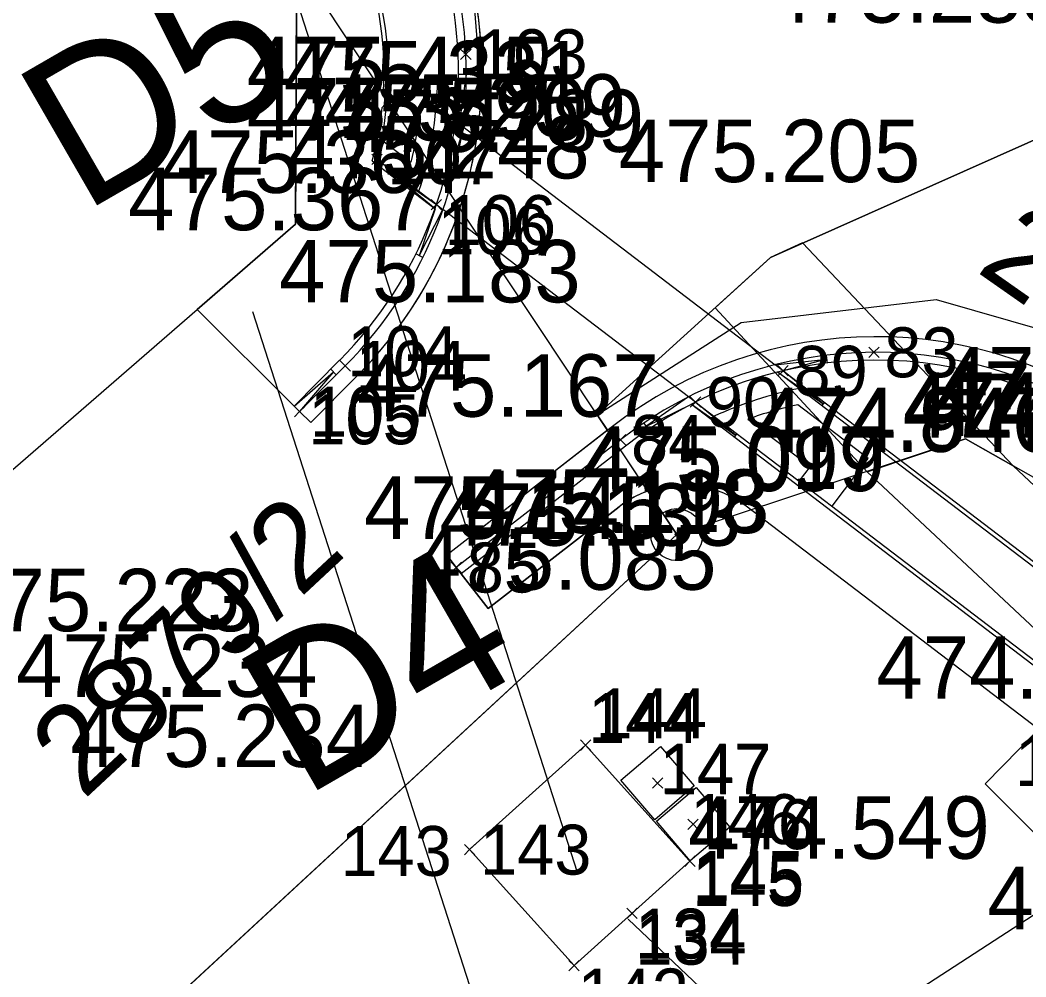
# Model space of a CAD drawing. Extents: x -758836 to -757729, y -1175316 to -1174366.
# Drawn here: x -758436.44 to -758417.1, y -1174844.78 to -1174826.39 of the extents above; entities that cross this region are included whole.
import ezdxf

# ---------------------------------------------------------------- set-up
doc = ezdxf.new("R2010")
doc.units = 0
for name, color, linetype in [('__NOR-dočasný zábor', 7, 'Continuous'), ('_NOR-návrh silná', 7, 'Continuous'), ('_NOR-návrh tenká', 7, 'Continuous'), ('_NOR-popis', 7, 'Continuous'), ('_vytyčený bod', 7, 'Continuous'), ('G_Obvod stavby', 7, 'Continuous'), ('Hranice parcel', 7, 'Continuous'), ('KOS_kabely SSZT', 7, 'Continuous'), ('KOS_PZZ nové', 7, 'Continuous'), ('Parcelní čísla', 7, 'Continuous'), ('Vnitřní kresba', 7, 'Continuous'), ('Vrstva 61', 7, 'Continuous'), ('Věcná břemena k části', 7, 'Continuous'), ('Značky bodu BP', 7, 'Continuous')]:
    doc.layers.add(name, color=color, linetype=linetype)

msp = doc.modelspace()

# ---------------------------------------------------------------- linework, layer by layer
at = {"layer": '__NOR-dočasný zábor'}
for p, q in [((-758431.14, -1174830.31), (-758431.12, -1174825.29)), ((-758433.036, -1174831.952), (-758431.14, -1174830.31)), ((-758431.169, -1174833.809), (-758433.036, -1174831.952)), ((-758429.975, -1174833.247), (-758430.85, -1174834.126)), ((-758431.063, -1174833.915), (-758431.169, -1174833.809)), ((-758430.85, -1174834.126), (-758431.063, -1174833.915)), ((-758425.144, -1174834.274), (-758428.234, -1174836.675)), ((-758424.978, -1174834.525), (-758425.144, -1174834.274)), ((-758424.894, -1174834.65), (-758424.978, -1174834.525)), ((-758424.368, -1174835.441), (-758424.894, -1174834.65)), ((-758428.234, -1174836.675), (-758428.05, -1174836.912)), ((-758428.05, -1174836.912), (-758427.958, -1174837.03))]:
    msp.add_line(p, q, dxfattribs=at)
msp.add_lwpolyline([(-758427.958, -1174837.03), (-758427.436, -1174837.702), (-758424.916, -1174835.743)], dxfattribs=at)
for centre, radius, start, end in [((-758435.859, -1174827.393), 8.3, 341.6371, 49.8317), ((-758435.859, -1174827.393), 8.3, 315.1499, 341.6371), ((-758423.689, -1174837.322), 2, 109.854, 127.8448)]:
    msp.add_arc(centre, radius, start, end, dxfattribs=at)
at = {"layer": '_NOR-návrh silná'}
for p, q in [((-758430.188, -1174833.035), (-758431.063, -1174833.915)), ((-758421.766, -1174833.13), (-758401.3, -1174848.727)), ((-758423.45, -1174833.732), (-758401.745, -1174850.274))]:
    msp.add_line(p, q, dxfattribs=at)
for points in [[(-758429.577, -1174829.063), (-758428.432, -1174829.935)], [(-758424.891, -1174834.458), (-758428.05, -1174836.912)]]:
    msp.add_lwpolyline(points, dxfattribs=at)
for centre, radius, start, end in [((-758435.859, -1174827.393), 8, 315.1499, 49.8317), ((-758435.859, -1174827.393), 6.5, 345.1172, 49.8317), ((-758419.983, -1174840.775), 8, 52.6885, 127.8448)]:
    msp.add_arc(centre, radius, start, end, dxfattribs=at)
at = {"layer": '_NOR-návrh tenká'}
for p, q in [((-758427.86, -1174827.437), (-758428.01, -1174827.437)), ((-758427.996, -1174828.382), (-758428.01, -1174827.437)), ((-758427.86, -1174827.437), (-758427.996, -1174828.382)), ((-758428.065, -1174828.329), (-758427.927, -1174828.434)), ((-758427.927, -1174828.434), (-758421.919, -1174833.013)), ((-758429.228, -1174829.329), (-758429.276, -1174829.393)), ((-758428.46, -1174830.015), (-758429.252, -1174829.361)), ((-758429.252, -1174829.361), (-758428.432, -1174829.935)), ((-758428.432, -1174829.935), (-758428.307, -1174830.031)), ((-758428.46, -1174830.015), (-758428.762, -1174830.918)), ((-758428.762, -1174830.918), (-758428.307, -1174830.031)), ((-758423.583, -1174833.631), (-758428.307, -1174830.031)), ((-758428.694, -1174830.952), (-758428.829, -1174830.885)), ((-758420.937, -1174832.832), (-758420.919, -1174832.981)), ((-758430.294, -1174832.929), (-758431.169, -1174833.809)), ((-758421.919, -1174833.013), (-758420.928, -1174832.907)), ((-758421.766, -1174833.13), (-758421.919, -1174833.013)), ((-758420.928, -1174832.907), (-758421.766, -1174833.13)), ((-758431.169, -1174833.809), (-758430.411, -1174833.153)), ((-758430.411, -1174833.153), (-758431.063, -1174833.915)), ((-758430.464, -1174833.1), (-758430.358, -1174833.206)), ((-758421.866, -1174833.154), (-758420.994, -1174833.768)), ((-758420.994, -1174833.768), (-758421.766, -1174833.13)), ((-758423.583, -1174833.631), (-758424.404, -1174834.198)), ((-758424.404, -1174834.198), (-758423.53, -1174833.772)), ((-758423.45, -1174833.732), (-758423.583, -1174833.631)), ((-758423.53, -1174833.772), (-758422.679, -1174834.37)), ((-758422.679, -1174834.37), (-758423.45, -1174833.732)), ((-758420.97, -1174833.736), (-758421.019, -1174833.8)), ((-758431.169, -1174833.809), (-758431.063, -1174833.915)), ((-758424.445, -1174834.135), (-758424.362, -1174834.26)), ((-758422.655, -1174834.338), (-758422.703, -1174834.402))]:
    msp.add_line(p, q, dxfattribs=at)
for points in [[(-758431.718, -1174822.487), (-758431.833, -1174822.623), (-758431.12, -1174825.29), (-758431.14, -1174830.31), (-758433.036, -1174831.952), (-758431.169, -1174833.809)], [(-758428.411, -1174827.562), (-758428.023, -1174827.858)], [(-758428.76, -1174828.24), (-758429.371, -1174827.774)], [(-758429.49, -1174828.689), (-758428.922, -1174829.122)], [(-758429.669, -1174829.094), (-758428.46, -1174830.015)], [(-758408.073, -1174843.666), (-758421.866, -1174833.154)], [(-758431.063, -1174833.915), (-758430.85, -1174834.126), (-758429.975, -1174833.247)], [(-758423.53, -1174833.772), (-758409.191, -1174844.7)], [(-758420.824, -1174835.734), (-758420.127, -1174834.819), (-758421.484, -1174833.785)], [(-758422.441, -1174834.061), (-758421.248, -1174834.97), (-758421.46, -1174835.249)], [(-758425.075, -1174834.221), (-758428.234, -1174836.675), (-758428.05, -1174836.912)], [(-758424.799, -1174834.576), (-758427.958, -1174837.03), (-758428.05, -1174836.912)], [(-758413.475, -1174842.592), (-758422.476, -1174835.732)], [(-758424.916, -1174835.743), (-758427.436, -1174837.702), (-758427.958, -1174837.03)]]:
    msp.add_lwpolyline(points, dxfattribs=at)
for centre, radius, start, end in [((-758435.859, -1174827.393), 8.3, 315.1499, 49.8317), ((-758435.859, -1174827.393), 7.85, 315.1499, 49.8317), ((-758435.859, -1174827.393), 6.42, 356.6281, 49.8317), ((-758435.859, -1174827.393), 7.45, 342.1323, 358.6977), ((-758429.595, -1174827.909), 0.2, 306.8376, 43.7466), ((-758435.859, -1174827.393), 6.42, 344.6403, 353.9561), ((-758435.859, -1174827.393), 7.15, 346.0044, 353.1985), ((-758419.983, -1174840.775), 8.3, 52.6885, 127.8448), ((-758419.983, -1174840.775), 7.85, 52.6885, 127.8448), ((-758419.983, -1174840.775), 7.45, 101.3579, 114.6673), ((-758419.983, -1174840.775), 7.15, 102.1205, 110.1095), ((-758423.689, -1174837.322), 2, 52.6885, 127.8448)]:
    msp.add_arc(centre, radius, start, end, dxfattribs=at)
at = {"layer": '_NOR-popis'}
for points in [[(-758436.507, -1174778.308), (-758445.549, -1174781.221), (-758425.724, -1174842.771)], [(-758421.971, -1174894), (-758412.929, -1174891.088), (-758431.963, -1174831.996)]]:
    msp.add_lwpolyline(points, dxfattribs=at)
at = {"layer": '_vytyčený bod'}
for p, q in [((-758427.867, -1174827.045), (-758427.967, -1174826.945)), ((-758427.867, -1174827.045), (-758427.767, -1174826.945)), ((-758427.867, -1174827.045), (-758427.967, -1174827.145)), ((-758427.867, -1174827.045), (-758427.767, -1174827.145)), ((-758429.578, -1174829.063), (-758429.678, -1174828.963)), ((-758429.578, -1174829.063), (-758429.478, -1174828.963)), ((-758429.578, -1174829.063), (-758429.678, -1174829.163)), ((-758429.578, -1174829.063), (-758429.478, -1174829.163)), ((-758428.432, -1174829.935), (-758428.532, -1174829.835)), ((-758428.432, -1174829.935), (-758428.532, -1174830.035)), ((-758428.432, -1174829.935), (-758428.332, -1174829.835)), ((-758428.432, -1174829.935), (-758428.332, -1174830.035)), ((-758420.02, -1174832.775), (-758420.12, -1174832.675)), ((-758420.02, -1174832.775), (-758420.12, -1174832.875)), ((-758420.02, -1174832.775), (-758419.92, -1174832.675)), ((-758420.02, -1174832.775), (-758419.92, -1174832.875)), ((-758430.188, -1174833.035), (-758430.288, -1174832.935)), ((-758430.188, -1174833.035), (-758430.088, -1174832.935)), ((-758421.766, -1174833.13), (-758421.866, -1174833.03)), ((-758421.766, -1174833.13), (-758421.666, -1174833.03)), ((-758430.188, -1174833.035), (-758430.288, -1174833.135)), ((-758430.188, -1174833.035), (-758430.088, -1174833.135)), ((-758421.766, -1174833.13), (-758421.866, -1174833.23)), ((-758421.766, -1174833.13), (-758421.666, -1174833.23)), ((-758423.45, -1174833.732), (-758423.55, -1174833.632)), ((-758423.45, -1174833.732), (-758423.55, -1174833.832)), ((-758423.45, -1174833.732), (-758423.35, -1174833.632)), ((-758423.45, -1174833.732), (-758423.35, -1174833.832)), ((-758431.063, -1174833.915), (-758431.163, -1174833.815)), ((-758431.063, -1174833.915), (-758431.163, -1174834.015)), ((-758431.063, -1174833.915), (-758430.963, -1174833.815)), ((-758431.063, -1174833.915), (-758430.963, -1174834.015)), ((-758424.891, -1174834.458), (-758424.991, -1174834.358)), ((-758424.891, -1174834.458), (-758424.791, -1174834.358)), ((-758424.891, -1174834.458), (-758424.991, -1174834.558)), ((-758424.891, -1174834.458), (-758424.791, -1174834.558)), ((-758428.05, -1174836.912), (-758428.15, -1174836.812)), ((-758428.05, -1174836.912), (-758427.95, -1174836.812)), ((-758428.05, -1174836.912), (-758428.15, -1174837.012)), ((-758428.05, -1174836.912), (-758427.95, -1174837.012)), ((-758425.565, -1174840.327), (-758425.665, -1174840.227)), ((-758425.565, -1174840.327), (-758425.665, -1174840.427)), ((-758425.565, -1174840.327), (-758425.465, -1174840.227)), ((-758425.565, -1174840.327), (-758425.465, -1174840.427)), ((-758424.179, -1174841.055), (-758424.279, -1174840.955)), ((-758424.179, -1174841.055), (-758424.079, -1174840.955)), ((-758424.179, -1174841.055), (-758424.279, -1174841.155)), ((-758424.179, -1174841.055), (-758424.079, -1174841.155)), ((-758423.496, -1174841.846), (-758423.596, -1174841.746)), ((-758423.496, -1174841.846), (-758423.596, -1174841.946)), ((-758423.496, -1174841.846), (-758423.396, -1174841.746)), ((-758423.496, -1174841.846), (-758423.396, -1174841.946)), ((-758427.794, -1174842.335), (-758427.894, -1174842.235)), ((-758427.794, -1174842.335), (-758427.694, -1174842.235)), ((-758427.794, -1174842.335), (-758427.894, -1174842.435)), ((-758427.794, -1174842.335), (-758427.694, -1174842.435)), ((-758423.557, -1174842.556), (-758423.657, -1174842.456)), ((-758423.557, -1174842.556), (-758423.457, -1174842.456)), ((-758423.557, -1174842.556), (-758423.657, -1174842.656)), ((-758423.557, -1174842.556), (-758423.457, -1174842.656)), ((-758424.671, -1174843.56), (-758424.771, -1174843.46)), ((-758424.671, -1174843.56), (-758424.571, -1174843.46)), ((-758424.671, -1174843.56), (-758424.771, -1174843.66)), ((-758424.671, -1174843.56), (-758424.571, -1174843.66)), ((-758425.786, -1174844.564), (-758425.886, -1174844.464)), ((-758425.786, -1174844.564), (-758425.886, -1174844.664)), ((-758425.786, -1174844.564), (-758425.686, -1174844.464)), ((-758425.786, -1174844.564), (-758425.686, -1174844.664))]:
    msp.add_line(p, q, dxfattribs=at)
at = {"layer": 'G_Obvod stavby'}
for p, q in [((-758431.14, -1174830.31), (-758431.12, -1174825.29)), ((-758433.036, -1174831.952), (-758431.14, -1174830.31)), ((-758431.169, -1174833.809), (-758433.036, -1174831.952)), ((-758429.975, -1174833.247), (-758430.85, -1174834.126)), ((-758431.063, -1174833.915), (-758431.169, -1174833.809)), ((-758430.85, -1174834.126), (-758431.063, -1174833.915)), ((-758425.144, -1174834.274), (-758428.234, -1174836.675)), ((-758428.234, -1174836.675), (-758428.05, -1174836.912)), ((-758428.05, -1174836.912), (-758427.958, -1174837.03))]:
    msp.add_line(p, q, dxfattribs=at)
for points in [[(-758410.628, -1174832.486), (-758416.41, -1174828.46), (-758422.01, -1174830.95), (-758425.34, -1174833.98), (-758425.144, -1174834.274)], [(-758424.368, -1174835.441), (-758423.81, -1174836.28), (-758457.56, -1174867.46)], [(-758427.958, -1174837.03), (-758427.436, -1174837.702), (-758424.916, -1174835.743)]]:
    msp.add_lwpolyline(points, dxfattribs=at)
for centre, radius, start, end in [((-758435.859, -1174827.393), 8.3, 341.6371, 49.8317), ((-758435.859, -1174827.393), 8.3, 315.1499, 341.6371), ((-758423.689, -1174837.322), 2, 109.854, 127.8448)]:
    msp.add_arc(centre, radius, start, end, dxfattribs=at)
at = {"layer": 'Hranice parcel'}
for p, q in [((-758431.14, -1174830.31), (-758431.12, -1174825.29)), ((-758462.28, -1174857.27), (-758431.14, -1174830.31)), ((-758423.81, -1174836.28), (-758425.34, -1174833.98)), ((-758457.56, -1174867.46), (-758423.81, -1174836.28))]:
    msp.add_line(p, q, dxfattribs=at)
for points in [[(-758425.34, -1174833.98), (-758428.26, -1174829.59), (-758431.12, -1174825.29)], [(-758425.34, -1174833.98), (-758422.01, -1174830.95), (-758416.41, -1174828.46), (-758408.08, -1174834.26)], [(-758408.08, -1174834.26), (-758411.08, -1174836.79), (-758412.3, -1174837.81), (-758418.26, -1174834.44), (-758423.81, -1174836.28)]]:
    msp.add_lwpolyline(points, dxfattribs=at)
at = {"layer": 'KOS_kabely SSZT'}
msp.add_lwpolyline([(-758393.377, -1174840.127), (-758394.523, -1174839.636), (-758402.059, -1174830.861), (-758402.489, -1174830.243), (-758402.873, -1174830.574), (-758402.896, -1174831.429), (-758411.837, -1174839.758), (-758412.685, -1174838.202), (-758411.837, -1174839.758), (-758414.56, -1174842.041), (-758415.093, -1174841.478), (-758414.56, -1174842.041), (-758421.625, -1174846.632), (-758424.748, -1174843.672)], dxfattribs=at)
at = {"layer": 'KOS_PZZ nové'}
for p, q in [((-758425.565, -1174840.327), (-758427.794, -1174842.335)), ((-758423.557, -1174842.556), (-758425.565, -1174840.327)), ((-758427.794, -1174842.335), (-758425.786, -1174844.564)), ((-758425.786, -1174844.564), (-758423.557, -1174842.556))]:
    msp.add_line(p, q, dxfattribs=at)
for points in [[(-758424.884, -1174840.998), (-758424.122, -1174840.35), (-758423.474, -1174841.111), (-758424.235, -1174841.76), (-758424.884, -1174840.998)], [(-758424.2, -1174841.79), (-758423.439, -1174841.142), (-758422.791, -1174841.903), (-758423.552, -1174842.551), (-758424.2, -1174841.79)]]:
    msp.add_lwpolyline(points, dxfattribs=at)
at = {"layer": 'Vnitřní kresba'}
for p, q in [((-758427.59, -1174827.47), (-758427.88, -1174823.96)), ((-758428.26, -1174829.59), (-758427.59, -1174827.47)), ((-758422.57, -1174832.2), (-758418.82, -1174831.76)), ((-758418.82, -1174831.76), (-758416.34, -1174832.47)), ((-758425.34, -1174833.98), (-758422.57, -1174832.2))]:
    msp.add_line(p, q, dxfattribs=at)
at = {"layer": 'Věcná břemena k části'}
for points in [[(-758420.15, -1174835.07), (-758418.26, -1174834.44), (-758417.34, -1174834.96), (-758421.39, -1174830.67), (-758422.01, -1174830.95), (-758423.07, -1174831.92)], [(-758403.27, -1174854.29), (-758401.71, -1174852.87), (-758403.96, -1174851.6), (-758406.91, -1174849.22), (-758415.06, -1174841.05), (-758413.04, -1174838.99), (-758417.34, -1174834.96), (-758418.26, -1174834.44), (-758420.15, -1174835.07), (-758415.9, -1174839.05), (-758417.88, -1174841.07), (-758408.25, -1174850.72), (-758405.08, -1174853.26)]]:
    msp.add_lwpolyline(points, close=True, dxfattribs=at)
at = {"layer": 'Značky bodu BP'}
for radius in [0.5, 0.0303]:
    msp.add_circle((-758423.81, -1174836.28), radius, dxfattribs=at)

# ---------------------------------------------------------------- texts
at = {"layer": '__NOR-dočasný zábor'}
for s, p in [('D5', (-758435.235, -1174830.11)), ('D4', (-758430.993, -1174841.35))]:
    msp.add_text(s, height=2.9088, rotation=30, dxfattribs=at).set_placement(p)
at = {"layer": '_vytyčený bod'}
for s, height, p in [('103', 0.9599, (-758427.667, -1174827.525)), ('103', 0.9596, (-758427.667, -1174827.525)), ('107', 0.9599, (-758429.378, -1174829.543)), ('107', 0.9596, (-758429.378, -1174829.543)), ('106', 0.9599, (-758428.273, -1174830.714)), ('106', 0.9596, (-758428.411, -1174830.893)), ('104', 0.9596, (-758430.15, -1174833.234)), ('83', 0.9599, (-758419.82, -1174833.255)), ('83', 0.9596, (-758419.82, -1174833.255)), ('104', 0.9599, (-758429.988, -1174833.515)), ('89', 0.9599, (-758421.566, -1174833.61)), ('89', 0.9596, (-758421.566, -1174833.61)), ('90', 0.9599, (-758423.25, -1174834.212)), ('90', 0.9596, (-758423.25, -1174834.212)), ('105', 0.9599, (-758430.895, -1174834.543)), ('105', 0.9596, (-758430.863, -1174834.395)), ('84', 0.9599, (-758424.691, -1174834.938)), ('84', 0.9596, (-758424.691, -1174834.938)), ('85', 0.9599, (-758427.85, -1174837.392)), ('85', 0.9596, (-758427.85, -1174837.392)), ('144', 0.9596, (-758425.515, -1174840.282)), ('144', 0.9599, (-758425.371, -1174840.195)), ('132', 0.9599, (-758417.307, -1174841.111)), ('147', 0.9596, (-758424.138, -1174841.26)), ('147', 0.9599, (-758424.131, -1174841.271)), ('146', 0.9596, (-758423.551, -1174842.228)), ('146', 0.9599, (-758423.296, -1174842.326)), ('143', 0.9596, (-758430.279, -1174842.84)), ('143', 0.9599, (-758427.594, -1174842.815)), ('145', 0.9596, (-758423.51, -1174843.419)), ('145', 0.9599, (-758423.505, -1174843.318)), ('134', 0.9599, (-758424.614, -1174844.428)), ('134', 0.9596, (-758424.606, -1174844.546)), ('142', 0.9599, (-758425.72, -1174845.58))]:
    msp.add_text(s, height=height, dxfattribs=at).set_placement(p)
at = {"layer": 'Parcelní čísla'}
for s, rotation, p in [('2879/19', 325, (-758418.077, -1174831.206)), ('2879/2', 43, (-758435.221, -1174841.391))]:
    msp.add_text(s, height=1.7, rotation=rotation, dxfattribs=at).set_placement(p)
at = {"layer": 'Vrstva 61'}
for s, p in [('475.285', (-758422.086, -1174826.439)), ('475.415', (-758432.08, -1174827.909)), ('475.331', (-758431.369, -1174827.989)), ('475.259', (-758430.585, -1174828.63)), ('475.347', (-758432.078, -1174828.705)), ('475.590', (-758431.336, -1174828.696)), ('475.289', (-758430.239, -1174828.924)), ('475.248', (-758431.285, -1174829.433)), ('475.205', (-758424.928, -1174829.503)), ('475.364', (-758433.734, -1174829.711)), ('475.367', (-758434.361, -1174830.428)), ('475.183', (-758431.459, -1174831.815)), ('475.167', (-758429.957, -1174834.013)), ('474.658', (-758418.714, -1174833.873)), ('474.517', (-758418.795, -1174834.146)), ('474.823', (-758419.464, -1174834.418)), ('474.677', (-758419.461, -1174834.36)), ('474.646', (-758418.989, -1174834.384)), ('474.847', (-758422.277, -1174834.652)), ('474.946', (-758422.272, -1174834.69)), ('475.017', (-758425.615, -1174835.401)), ('475.099', (-758425.605, -1174835.443)), ('475.118', (-758427.873, -1174836.226)), ('475.193', (-758427.83, -1174836.251)), ('475.145', (-758429.826, -1174836.361)), ('475.133', (-758428.373, -1174836.493)), ('475.085', (-758428.848, -1174837.339)), ('475.223', (-758437.748, -1174838.137)), ('475.234', (-758436.519, -1174839.398)), ('474.729', (-758419.973, -1174839.433)), ('475.234', (-758435.47, -1174840.746)), ('474.549', (-758423.591, -1174842.511)), ('474.380', (-758417.836, -1174843.865))]:
    msp.add_text(s, height=1.2, dxfattribs=at).set_placement(p)

doc.saveas('drawing.dxf')
